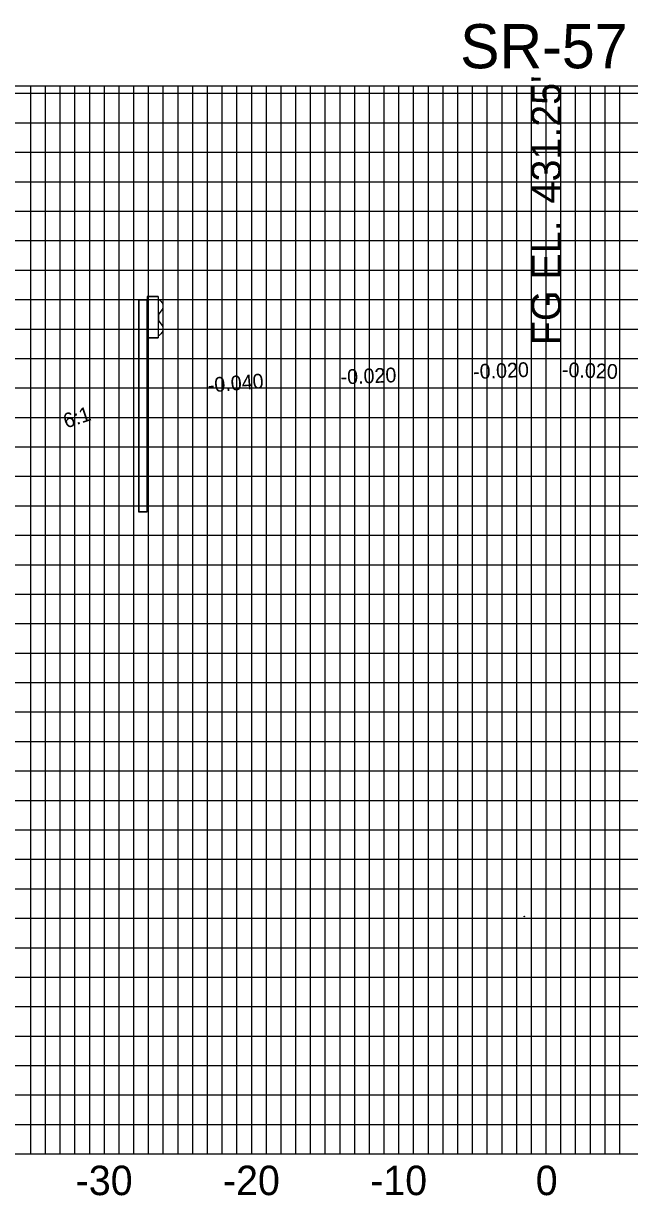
# Model space of a CAD drawing. Extents: x -158 to 158, y 398 to 482.
# Drawn here: x -35.5 to 5.7, y 402.2 to 481.7 of the extents above; entities that cross this region are included whole.
import ezdxf

# ---------------------------------------------------------------- set-up
doc = ezdxf.new("R2010")
doc.units = 0
for name, color, linetype in [('Default', 7, 'Continuous'), ('DES - CL - Proposed Text', 7, 'Continuous'), ('DES - SCRATCH - User 1', 7, 'Continuous'), ('DES - SHEET - Corner Text', 7, 'Continuous'), ('DES - SHEET - Revision Text', 7, 'Continuous'), ('SUR - DTM - Spot Points', 7, 'Continuous'), ('SUR - PROPERTY - Owners', 7, 'Continuous')]:
    doc.layers.add(name, color=color, linetype=linetype)

msp = doc.modelspace()

# ---------------------------------------------------------------- linework, layer by layer
at = {"layer": 'Default'}
msp.add_ellipse((-1.484, 421.125), major_axis=(0, 0.024), ratio=0.5, dxfattribs=at)
msp.add_ellipse((-1.484, 421.125), major_axis=(0, 0.024), ratio=0.5, dxfattribs=at)
msp.add_ellipse((-1.484, 421.125), major_axis=(0, 0.024), ratio=0.5, dxfattribs=at)
at = {"layer": 'DES - SCRATCH - User 1'}
for p, q in [((-150, 477.499), (150, 477.499)), ((-150, 477.499), (150, 477.499)), ((-150, 477.499), (150, 477.499)), ((-30, 405), (-30, 477.499)), ((-30, 405), (-30, 477.499)), ((-30, 405), (-30, 477.499)), ((-20, 405), (-20, 477.499)), ((-20, 405), (-20, 477.499)), ((-20, 405), (-20, 477.499)), ((-10, 405), (-10, 477.499)), ((-10, 405), (-10, 477.499)), ((-10, 405), (-10, 477.499)), ((0, 405), (0, 477.499)), ((0, 405), (0, 477.499)), ((0, 405), (0, 477.499)), ((-150, 475), (150, 475)), ((-150, 475), (150, 475)), ((-150, 475), (150, 475)), ((-150, 455), (150, 455)), ((-150, 455), (150, 455)), ((-150, 455), (150, 455)), ((-150, 435), (150, 435)), ((-150, 435), (150, 435)), ((-150, 435), (150, 435)), ((-150, 415), (150, 415)), ((-150, 415), (150, 415)), ((-150, 415), (150, 415)), ((-150, 405), (150, 405)), ((-150, 405), (150, 405)), ((-150, 405), (150, 405))]:
    msp.add_line(p, q, dxfattribs=at)
at = {"layer": 'DES - SHEET - Corner Text'}
for p, q in [((-35, 405), (-35, 477.499)), ((-35, 405), (-35, 477.499)), ((-35, 405), (-35, 477.499)), ((-34, 405), (-34, 477.499)), ((-34, 405), (-34, 477.499)), ((-34, 405), (-34, 477.499)), ((-33, 405), (-33, 477.499)), ((-33, 405), (-33, 477.499)), ((-33, 405), (-33, 477.499)), ((-32, 405), (-32, 477.499)), ((-32, 405), (-32, 477.499)), ((-32, 405), (-32, 477.499)), ((-31, 405), (-31, 477.499)), ((-31, 405), (-31, 477.499)), ((-31, 405), (-31, 477.499)), ((-29, 405), (-29, 477.499)), ((-29, 405), (-29, 477.499)), ((-29, 405), (-29, 477.499)), ((-28, 405), (-28, 477.499)), ((-28, 405), (-28, 477.499)), ((-28, 405), (-28, 477.499)), ((-27, 405), (-27, 477.499)), ((-27, 405), (-27, 477.499)), ((-27, 405), (-27, 477.499)), ((-26, 405), (-26, 477.499)), ((-26, 405), (-26, 477.499)), ((-26, 405), (-26, 477.499)), ((-25, 405), (-25, 477.499)), ((-25, 405), (-25, 477.499)), ((-25, 405), (-25, 477.499)), ((-24, 405), (-24, 477.499)), ((-24, 405), (-24, 477.499)), ((-24, 405), (-24, 477.499)), ((-23, 405), (-23, 477.499)), ((-23, 405), (-23, 477.499)), ((-23, 405), (-23, 477.499)), ((-22, 405), (-22, 477.499)), ((-22, 405), (-22, 477.499)), ((-22, 405), (-22, 477.499)), ((-21, 405), (-21, 477.499)), ((-21, 405), (-21, 477.499)), ((-21, 405), (-21, 477.499)), ((-19, 405), (-19, 477.499)), ((-19, 405), (-19, 477.499)), ((-19, 405), (-19, 477.499)), ((-18, 405), (-18, 477.499)), ((-18, 405), (-18, 477.499)), ((-18, 405), (-18, 477.499)), ((-17, 405), (-17, 477.499)), ((-17, 405), (-17, 477.499)), ((-17, 405), (-17, 477.499)), ((-16, 405), (-16, 477.499)), ((-16, 405), (-16, 477.499)), ((-16, 405), (-16, 477.499)), ((-15, 405), (-15, 477.499)), ((-15, 405), (-15, 477.499)), ((-15, 405), (-15, 477.499)), ((-14, 405), (-14, 477.499)), ((-14, 405), (-14, 477.499)), ((-14, 405), (-14, 477.499)), ((-13, 405), (-13, 477.499)), ((-13, 405), (-13, 477.499)), ((-13, 405), (-13, 477.499)), ((-12, 405), (-12, 477.499)), ((-12, 405), (-12, 477.499)), ((-12, 405), (-12, 477.499)), ((-11, 405), (-11, 477.499)), ((-11, 405), (-11, 477.499)), ((-11, 405), (-11, 477.499)), ((-9, 405), (-9, 477.499)), ((-9, 405), (-9, 477.499)), ((-9, 405), (-9, 477.499)), ((-8, 405), (-8, 477.499)), ((-8, 405), (-8, 477.499)), ((-8, 405), (-8, 477.499)), ((-7, 405), (-7, 477.499)), ((-7, 405), (-7, 477.499)), ((-7, 405), (-7, 477.499)), ((-6, 405), (-6, 477.499)), ((-6, 405), (-6, 477.499)), ((-6, 405), (-6, 477.499)), ((-5, 405), (-5, 477.499)), ((-5, 405), (-5, 477.499)), ((-5, 405), (-5, 477.499)), ((-4, 405), (-4, 477.499)), ((-4, 405), (-4, 477.499)), ((-4, 405), (-4, 477.499)), ((-3, 405), (-3, 477.499)), ((-3, 405), (-3, 477.499)), ((-3, 405), (-3, 477.499)), ((-2, 405), (-2, 477.499)), ((-2, 405), (-2, 477.499)), ((-2, 405), (-2, 477.499)), ((-1, 405), (-1, 477.499)), ((-1, 405), (-1, 477.499)), ((-1, 405), (-1, 477.499)), ((1, 405), (1, 477.499)), ((1, 405), (1, 477.499)), ((1, 405), (1, 477.499)), ((2, 405), (2, 477.499)), ((2, 405), (2, 477.499)), ((2, 405), (2, 477.499)), ((3, 405), (3, 477.499)), ((3, 405), (3, 477.499)), ((3, 405), (3, 477.499)), ((4, 405), (4, 477.499)), ((4, 405), (4, 477.499)), ((4, 405), (4, 477.499)), ((5, 405), (5, 477.499)), ((5, 405), (5, 477.499)), ((5, 405), (5, 477.499)), ((-150, 477), (150, 477)), ((-150, 477), (150, 477)), ((-150, 477), (150, 477)), ((-150, 473), (150, 473)), ((-150, 473), (150, 473)), ((-150, 473), (150, 473)), ((-150, 471), (150, 471)), ((-150, 471), (150, 471)), ((-150, 471), (150, 471)), ((-150, 469), (150, 469)), ((-150, 469), (150, 469)), ((-150, 469), (150, 469)), ((-150, 467), (150, 467)), ((-150, 467), (150, 467)), ((-150, 467), (150, 467)), ((-150, 465), (150, 465)), ((-150, 465), (150, 465)), ((-150, 465), (150, 465)), ((-150, 463), (150, 463)), ((-150, 463), (150, 463)), ((-150, 463), (150, 463)), ((-150, 461), (150, 461)), ((-150, 461), (150, 461)), ((-150, 461), (150, 461)), ((-150, 459), (150, 459)), ((-150, 459), (150, 459)), ((-150, 459), (150, 459)), ((-150, 457), (150, 457)), ((-150, 457), (150, 457)), ((-150, 457), (150, 457)), ((-150, 453), (150, 453)), ((-150, 453), (150, 453)), ((-150, 453), (150, 453)), ((-150, 451), (150, 451)), ((-150, 451), (150, 451)), ((-150, 451), (150, 451)), ((-150, 449), (150, 449)), ((-150, 449), (150, 449)), ((-150, 449), (150, 449)), ((-150, 447), (150, 447)), ((-150, 447), (150, 447)), ((-150, 447), (150, 447)), ((-150, 445), (150, 445)), ((-150, 445), (150, 445)), ((-150, 445), (150, 445)), ((-150, 443), (150, 443)), ((-150, 443), (150, 443)), ((-150, 443), (150, 443)), ((-150, 441), (150, 441)), ((-150, 441), (150, 441)), ((-150, 441), (150, 441)), ((-150, 439), (150, 439)), ((-150, 439), (150, 439)), ((-150, 439), (150, 439)), ((-150, 437), (150, 437)), ((-150, 437), (150, 437)), ((-150, 437), (150, 437)), ((-150, 433), (150, 433)), ((-150, 433), (150, 433)), ((-150, 433), (150, 433)), ((-150, 431), (150, 431)), ((-150, 431), (150, 431)), ((-150, 431), (150, 431)), ((-150, 429), (150, 429)), ((-150, 429), (150, 429)), ((-150, 429), (150, 429)), ((-150, 427), (150, 427)), ((-150, 427), (150, 427)), ((-150, 427), (150, 427)), ((-150, 425), (150, 425)), ((-150, 425), (150, 425)), ((-150, 425), (150, 425)), ((-150, 423), (150, 423)), ((-150, 423), (150, 423)), ((-150, 423), (150, 423)), ((-150, 421), (150, 421)), ((-150, 421), (150, 421)), ((-150, 421), (150, 421)), ((-150, 419), (150, 419)), ((-150, 419), (150, 419)), ((-150, 419), (150, 419)), ((-150, 417), (150, 417)), ((-150, 417), (150, 417)), ((-150, 417), (150, 417)), ((-150, 413), (150, 413)), ((-150, 413), (150, 413)), ((-150, 413), (150, 413)), ((-150, 411), (150, 411)), ((-150, 411), (150, 411)), ((-150, 411), (150, 411)), ((-150, 409), (150, 409)), ((-150, 409), (150, 409)), ((-150, 409), (150, 409)), ((-150, 407), (150, 407)), ((-150, 407), (150, 407)), ((-150, 407), (150, 407))]:
    msp.add_line(p, q, dxfattribs=at)
at = {"layer": 'SUR - DTM - Spot Points'}
for p, q in [((-26.344, 463.202), (-27.094, 463.202)), ((-27.094, 463.202), (-27.094, 463.202)), ((-27.094, 463.202), (-26.344, 463.202)), ((-27.094, 463.202), (-27.094, 460.402)), ((-27.094, 463.202), (-27.094, 460.402)), ((-26.344, 463.202), (-27.094, 463.202)), ((-27.094, 463.202), (-27.094, 463.202)), ((-27.094, 463.202), (-26.344, 463.202)), ((-27.094, 463.202), (-27.094, 460.402)), ((-27.094, 463.202), (-27.094, 460.402)), ((-26.344, 463.202), (-27.094, 463.202)), ((-27.094, 463.202), (-27.094, 463.202)), ((-27.094, 463.202), (-26.344, 463.202)), ((-27.094, 463.202), (-27.094, 460.402)), ((-27.094, 463.202), (-27.094, 460.402)), ((-26.344, 463.202), (-26.344, 463.202)), ((-26.344, 463.202), (-26.344, 460.402)), ((-26.344, 463.202), (-26.344, 460.402)), ((-26.344, 463.202), (-26.344, 463.202)), ((-26.344, 463.202), (-26.344, 460.402)), ((-26.344, 463.202), (-26.344, 460.402)), ((-26.344, 463.202), (-26.344, 463.202)), ((-26.344, 463.202), (-26.344, 460.402)), ((-26.344, 463.202), (-26.344, 460.402)), ((-27.658, 462.979), (-27.677, 462.979)), ((-27.677, 462.979), (-27.677, 462.979)), ((-27.677, 462.979), (-27.658, 462.979)), ((-27.677, 462.979), (-27.677, 448.579)), ((-27.677, 462.979), (-27.677, 448.579)), ((-27.658, 462.979), (-27.677, 462.979)), ((-27.677, 462.979), (-27.677, 462.979)), ((-27.677, 462.979), (-27.658, 462.979)), ((-27.677, 462.979), (-27.677, 448.579)), ((-27.677, 462.979), (-27.677, 448.579)), ((-27.658, 462.979), (-27.677, 462.979)), ((-27.677, 462.979), (-27.677, 462.979)), ((-27.677, 462.979), (-27.658, 462.979)), ((-27.677, 462.979), (-27.677, 448.579)), ((-27.677, 462.979), (-27.677, 448.579)), ((-27.113, 462.979), (-27.658, 462.979)), ((-27.658, 462.979), (-27.658, 462.979)), ((-27.658, 462.979), (-27.658, 462.979)), ((-27.658, 462.979), (-27.113, 462.979)), ((-27.658, 462.979), (-27.658, 448.579)), ((-27.658, 462.979), (-27.658, 448.579)), ((-27.658, 462.979), (-27.658, 448.579)), ((-27.658, 462.979), (-27.658, 448.579)), ((-27.113, 462.979), (-27.658, 462.979)), ((-27.658, 462.979), (-27.658, 462.979)), ((-27.658, 462.979), (-27.658, 462.979)), ((-27.658, 462.979), (-27.113, 462.979)), ((-27.658, 462.979), (-27.658, 448.579)), ((-27.658, 462.979), (-27.658, 448.579)), ((-27.658, 462.979), (-27.658, 448.579)), ((-27.658, 462.979), (-27.658, 448.579)), ((-27.113, 462.979), (-27.658, 462.979)), ((-27.658, 462.979), (-27.658, 462.979)), ((-27.658, 462.979), (-27.658, 462.979)), ((-27.658, 462.979), (-27.113, 462.979)), ((-27.658, 462.979), (-27.658, 448.579)), ((-27.658, 462.979), (-27.658, 448.579)), ((-27.658, 462.979), (-27.658, 448.579)), ((-27.658, 462.979), (-27.658, 448.579)), ((-27.094, 462.979), (-27.113, 462.979)), ((-27.113, 462.979), (-27.113, 462.979)), ((-27.113, 462.979), (-27.113, 462.979)), ((-27.113, 462.979), (-27.094, 462.979)), ((-27.113, 462.979), (-27.113, 448.579)), ((-27.113, 462.979), (-27.113, 448.579)), ((-27.113, 462.979), (-27.113, 448.579)), ((-27.113, 462.979), (-27.113, 448.579)), ((-27.094, 462.979), (-27.113, 462.979)), ((-27.113, 462.979), (-27.113, 462.979)), ((-27.113, 462.979), (-27.113, 462.979)), ((-27.113, 462.979), (-27.094, 462.979)), ((-27.113, 462.979), (-27.113, 448.579)), ((-27.113, 462.979), (-27.113, 448.579)), ((-27.113, 462.979), (-27.113, 448.579)), ((-27.113, 462.979), (-27.113, 448.579)), ((-27.094, 462.979), (-27.113, 462.979)), ((-27.113, 462.979), (-27.113, 462.979)), ((-27.113, 462.979), (-27.113, 462.979)), ((-27.113, 462.979), (-27.094, 462.979)), ((-27.113, 462.979), (-27.113, 448.579)), ((-27.113, 462.979), (-27.113, 448.579)), ((-27.113, 462.979), (-27.113, 448.579)), ((-27.113, 462.979), (-27.113, 448.579)), ((-27.094, 462.979), (-27.094, 462.979)), ((-27.094, 462.979), (-27.094, 448.579)), ((-27.094, 462.979), (-27.094, 448.579)), ((-27.094, 462.979), (-27.094, 462.979)), ((-27.094, 462.979), (-27.094, 448.579)), ((-27.094, 462.979), (-27.094, 448.579)), ((-27.094, 462.979), (-27.094, 462.979)), ((-27.094, 462.979), (-27.094, 448.579)), ((-27.094, 462.979), (-27.094, 448.579)), ((-26.332, 463.004), (-26.293, 462.99)), ((-26.332, 463.004), (-26.293, 462.991)), ((-26.332, 463.004), (-26.293, 462.991)), ((-26.04, 462.398), (-26.292, 462.045)), ((-26.04, 462.398), (-26.292, 462.045)), ((-26.04, 462.398), (-26.292, 462.045)), ((-26.173, 462.891), (-26.04, 462.705)), ((-26.173, 462.891), (-26.04, 462.705)), ((-26.173, 462.891), (-26.04, 462.705)), ((-26.332, 461.892), (-26.332, 461.667)), ((-26.332, 461.892), (-26.332, 461.667)), ((-26.332, 461.892), (-26.332, 461.667)), ((-26.292, 461.513), (-26.04, 461.16)), ((-26.292, 461.513), (-26.04, 461.161)), ((-26.292, 461.513), (-26.04, 461.161)), ((-26.04, 460.853), (-26.173, 460.667)), ((-26.04, 460.853), (-26.173, 460.668)), ((-26.04, 460.853), (-26.173, 460.668)), ((-26.344, 460.402), (-27.094, 460.402)), ((-27.094, 460.402), (-27.094, 460.402)), ((-27.094, 460.402), (-26.344, 460.402)), ((-26.344, 460.402), (-27.094, 460.402)), ((-27.094, 460.402), (-27.094, 460.402)), ((-27.094, 460.402), (-26.344, 460.402)), ((-26.344, 460.402), (-27.094, 460.402)), ((-27.094, 460.402), (-27.094, 460.402)), ((-27.094, 460.402), (-26.344, 460.402)), ((-26.344, 460.402), (-26.344, 460.402)), ((-26.344, 460.402), (-26.344, 460.402)), ((-26.344, 460.402), (-26.344, 460.402)), ((-26.293, 460.568), (-26.332, 460.554)), ((-26.293, 460.568), (-26.332, 460.554)), ((-26.293, 460.568), (-26.332, 460.554)), ((-27.658, 448.579), (-27.677, 448.579)), ((-27.677, 448.579), (-27.677, 448.579)), ((-27.677, 448.579), (-27.658, 448.579)), ((-27.658, 448.579), (-27.677, 448.579)), ((-27.677, 448.579), (-27.677, 448.579)), ((-27.677, 448.579), (-27.658, 448.579)), ((-27.658, 448.579), (-27.677, 448.579)), ((-27.677, 448.579), (-27.677, 448.579)), ((-27.677, 448.579), (-27.658, 448.579)), ((-27.113, 448.579), (-27.658, 448.579)), ((-27.658, 448.579), (-27.658, 448.579)), ((-27.658, 448.579), (-27.658, 448.579)), ((-27.658, 448.579), (-27.113, 448.579)), ((-27.113, 448.579), (-27.658, 448.579)), ((-27.658, 448.579), (-27.658, 448.579)), ((-27.658, 448.579), (-27.658, 448.579)), ((-27.658, 448.579), (-27.113, 448.579)), ((-27.113, 448.579), (-27.658, 448.579)), ((-27.658, 448.579), (-27.658, 448.579)), ((-27.658, 448.579), (-27.658, 448.579)), ((-27.658, 448.579), (-27.113, 448.579)), ((-27.094, 448.579), (-27.113, 448.579)), ((-27.113, 448.579), (-27.113, 448.579)), ((-27.113, 448.579), (-27.113, 448.579)), ((-27.113, 448.579), (-27.094, 448.579)), ((-27.094, 448.579), (-27.113, 448.579)), ((-27.113, 448.579), (-27.113, 448.579)), ((-27.113, 448.579), (-27.113, 448.579)), ((-27.113, 448.579), (-27.094, 448.579)), ((-27.094, 448.579), (-27.113, 448.579)), ((-27.113, 448.579), (-27.113, 448.579)), ((-27.113, 448.579), (-27.113, 448.579)), ((-27.113, 448.579), (-27.094, 448.579)), ((-27.094, 448.579), (-27.094, 448.579)), ((-27.094, 448.579), (-27.094, 448.579)), ((-27.094, 448.579), (-27.094, 448.579))]:
    msp.add_line(p, q, dxfattribs=at)
for centre, major_axis, start_param, end_param in [((-26.345, 462.4), (0, 0.6), 5.67232, 6.108652), ((-26.345, 462.4), (0, 0.6), 5.67232, 6.108652), ((-26.345, 462.399), (0, 0.6), 5.67232, 6.108652), ((-26.094, 462.552), (0, 0.188), 3.752458, 5.67232), ((-26.094, 462.552), (0, 0.188), 3.752458, 5.67232), ((-26.094, 462.552), (0, 0.188), 3.752458, 5.67232), ((-26.238, 461.892), (0, 0.188), 0.610865, 1.570796), ((-26.238, 461.892), (0, 0.188), 0.610865, 1.570796), ((-26.238, 461.892), (0, 0.188), 0.610865, 1.570796), ((-26.238, 461.667), (0, -0.188), 4.712389, 5.67232), ((-26.238, 461.667), (0, -0.188), 4.712389, 5.67232), ((-26.238, 461.667), (0, -0.188), 4.712389, 5.67232), ((-26.094, 461.007), (0, 0.188), 3.752458, 5.67232), ((-26.094, 461.007), (0, 0.188), 3.752458, 5.67232), ((-26.094, 461.007), (0, 0.188), 3.752458, 5.67232), ((-26.345, 461.159), (0, -0.6), 0.174533, 0.610865), ((-26.345, 461.159), (0, -0.6), 0.174533, 0.610865), ((-26.345, 461.159), (0, -0.6), 0.174533, 0.610865)]:
    msp.add_ellipse(centre, major_axis=major_axis, ratio=0.5, start_param=start_param, end_param=end_param, dxfattribs=at)
at = {"layer": 'SUR - PROPERTY - Owners'}
msp.add_ellipse((-1.484, 421.125), major_axis=(0, 0.024), ratio=0.5, dxfattribs=at)
msp.add_ellipse((-1.484, 421.125), major_axis=(0, 0.024), ratio=0.5, dxfattribs=at)
msp.add_ellipse((-1.484, 421.125), major_axis=(0, 0.024), ratio=0.5, dxfattribs=at)
msp.add_ellipse((-1.484, 421.125), major_axis=(0, 0.024), ratio=0.5, dxfattribs=at)
msp.add_ellipse((-1.484, 421.125), major_axis=(0, 0.024), ratio=0.5, dxfattribs=at)
msp.add_ellipse((-1.484, 421.125), major_axis=(0, 0.024), ratio=0.5, dxfattribs=at)

# ---------------------------------------------------------------- texts
at = {"layer": 'DES - CL - Proposed Text'}
for s, rotation, p in [('-0.020', 2.29061, (-13.945, 457.241)), ('-0.020', 2.29061, (-13.945, 457.241)), ('-0.020', 2.29061, (-13.945, 457.241)), ('-0.020', 2.29061, (-4.945, 457.601)), ('-0.020', 2.29061, (-4.945, 457.601)), ('-0.020', 2.29061, (-4.945, 457.601)), ('-0.020', 357.70939, (1.055, 457.757)), ('-0.020', 357.70939, (1.055, 457.757)), ('-0.020', 357.70939, (1.055, 457.757)), ('-0.040', 4.57392, (-22.94, 456.684)), ('-0.040', 4.57392, (-22.94, 456.684)), ('-0.040', 4.57392, (-22.94, 456.684)), ('6:1', 18.43839, (-32.596, 454.24)), ('6:1', 18.43839, (-32.596, 454.24)), ('6:1', 18.43839, (-32.596, 454.24))]:
    msp.add_text(s, height=1, rotation=rotation, dxfattribs=at).set_placement(p)
at = {"layer": 'DES - SHEET - Revision Text'}
for s, height, p in [('SR-57', 3, (-5.845, 478.699)), ('SR-57', 3, (-5.845, 478.699)), ('SR-57', 3, (-5.845, 478.699)), ('SR-57', 3, (-5.845, 478.699)), ('SR-57', 3, (-5.845, 478.699)), ('-30', 2, (-31.951, 402.2)), ('-30', 2, (-31.951, 402.2)), ('-30', 2, (-31.951, 402.2)), ('-20', 2, (-21.951, 402.2)), ('-20', 2, (-21.951, 402.2)), ('-20', 2, (-21.951, 402.2)), ('-10', 2, (-11.951, 402.2)), ('-10', 2, (-11.951, 402.2)), ('-10', 2, (-11.951, 402.2)), ('0', 2, (-0.71, 402.2)), ('0', 2, (-0.71, 402.2)), ('0', 2, (-0.71, 402.2))]:
    msp.add_text(s, height=height, dxfattribs=at).set_placement(p)
for s, p in [("431.25'", (1, 469.526)), ("431.25'", (1, 469.526)), ("431.25'", (1, 469.526)), ("431.25'", (1, 469.526)), ("431.25'", (1, 469.526)), ('FG EL. ', (1, 459.899)), ('FG EL. ', (1, 459.899)), ('FG EL. ', (1, 459.899)), ('FG EL. ', (1, 459.899)), ('FG EL. ', (1, 459.899))]:
    msp.add_text(s, height=2, rotation=90, dxfattribs=at).set_placement(p)

doc.saveas('drawing.dxf')
